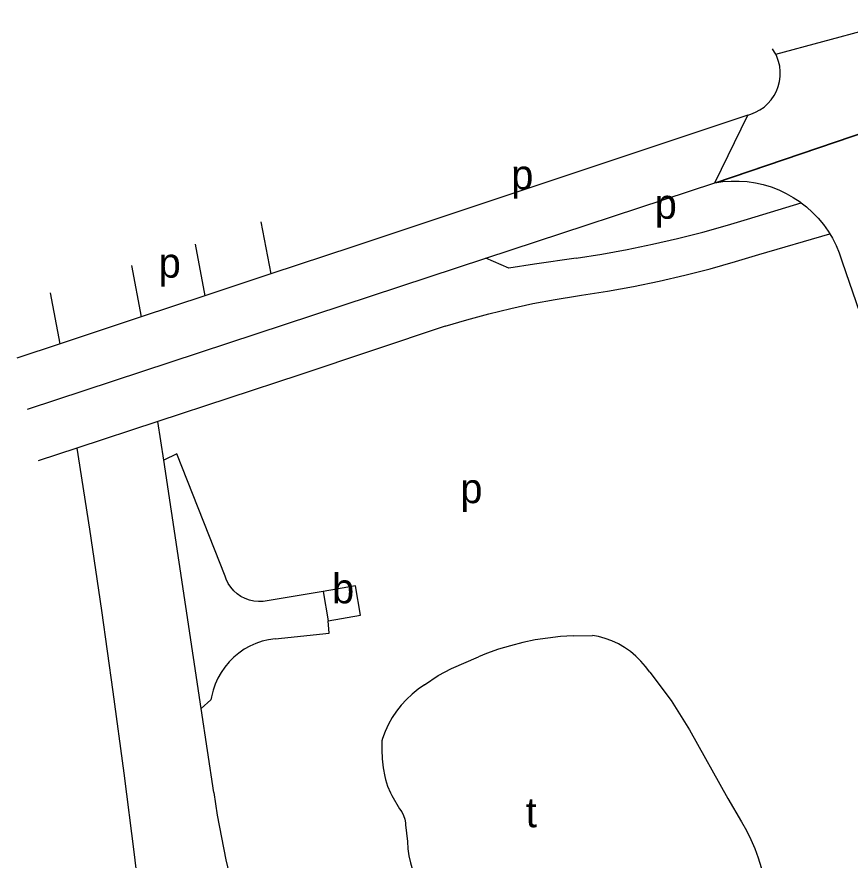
# Model space of a CAD drawing. Extents: x 161936 to 163647, y 386450 to 388633.
# Drawn here: x 162087.7 to 162199.4, y 388398.4 to 388511.6 of the extents above; entities that cross this region are included whole.
import ezdxf

# ---------------------------------------------------------------- set-up
doc = ezdxf.new("R2010")
doc.units = 0
for name, color, linetype in [('BLT_Basislijn', 7, 'Continuous'), ('BLT_Bebouwing', 7, 'Continuous'), ('BLT_Centroide', 7, 'Continuous'), ('BLT_Vlakafsluiter', 7, 'Continuous')]:
    doc.layers.add(name, color=color, linetype=linetype)

msp = doc.modelspace()

# ---------------------------------------------------------------- linework, layer by layer
at = {"layer": 'BLT_Basislijn'}
for p, q in [((162185.68, 388484.43), (162192.85, 388486.62)), ((162187.18, 388479.66), (162196.71, 388482.43)), ((162198.38, 388478.67), (162217.49, 388422.65)), ((162145.13, 388470.05), (162125.65, 388463.55)), ((162125.65, 388463.55), (162106.61, 388457.28)), ((162106.61, 388457.28), (162095.76, 388453.7)), ((162107.4, 388452.07), (162106.61, 388457.28)), ((162095.76, 388453.7), (162090.58, 388451.99)), ((162112.42, 388418.77), (162107.4, 388452.07)), ((162128.79, 388434.47), (162120.72, 388433.13)), ((162162.28, 388428.52), (162164.88, 388428.58)), ((162113.73, 388419.92), (162112.42, 388418.77)), ((162114.11, 388407.51), (162112.42, 388418.77)), ((162137.96, 388407.11), (162139.02, 388405.31)), ((162183.05, 388406.69), (162184.87, 388403.57)), ((162139.82, 388403.19), (162140.1, 388400.92))]:
    msp.add_line(p, q, dxfattribs=at)
for points in [[(162189.46, 388506.53), (162189.31, 388506.83), (162189.03, 388507.27)], [(162185.69, 388498.37), (162186.11, 388498.49), (162186.74, 388498.75), (162187.34, 388499.07), (162187.9, 388499.46), (162188.4, 388499.92), (162188.85, 388500.43), (162189.23, 388500.99), (162189.55, 388501.59), (162189.79, 388502.23), (162189.96, 388502.89), (162190.05, 388503.56), (162190.06, 388504.24), (162189.99, 388504.92), (162189.84, 388505.58), (162189.61, 388506.22), (162189.46, 388506.53)], [(162185.69, 388498.37), (162132.73, 388480.72), (162121.74, 388477.08)], [(162150.58, 388479.17), (162181.28, 388489.3)], [(162181.28, 388489.3), (162181.55, 388489.34)], [(162181.55, 388489.34), (162182.36, 388489.45), (162183.46, 388489.53), (162184.55, 388489.53), (162185.64, 388489.45), (162186.72, 388489.29), (162187.79, 388489.05), (162188.84, 388488.73), (162189.86, 388488.34), (162190.85, 388487.87), (162191.81, 388487.33), (162192.72, 388486.73), (162192.85, 388486.62)], [(162192.85, 388486.62), (162193.58, 388486.05), (162194.4, 388485.32), (162195.15, 388484.53), (162195.85, 388483.69), (162196.49, 388482.8), (162196.71, 388482.43)], [(162162.71, 388479.16), (162166.13, 388479.71), (162169.53, 388480.33), (162172.93, 388481.04), (162176.3, 388481.82), (162179.66, 388482.68), (162182.99, 388483.61), (162185.68, 388484.43)], [(162120.42, 388484.06), (162121.74, 388477.08)], [(162196.71, 388482.43), (162197.05, 388481.86), (162197.55, 388480.89), (162197.98, 388479.88), (162198.33, 388478.84), (162198.38, 388478.67)], [(162111.61, 388481.08), (162112.92, 388474.15)], [(162089.14, 388458.91), (162150.58, 388479.17)], [(162162.71, 388479.16), (162157.09, 388478.39), (162153.65, 388477.84), (162150.58, 388479.17)], [(162163.43, 388474.22), (162166.91, 388474.77), (162170.38, 388475.4), (162173.83, 388476.11), (162177.26, 388476.9), (162180.67, 388477.77), (162184.06, 388478.72), (162187.18, 388479.66)], [(162103.05, 388478.18), (162104.35, 388471.31)], [(162121.74, 388477.08), (162112.92, 388474.15)], [(162093.49, 388467.71), (162092.2, 388474.51)], [(162112.92, 388474.15), (162104.35, 388471.31)], [(162145.13, 388470.05), (162148.04, 388470.92), (162150.97, 388471.72), (162153.92, 388472.44), (162156.89, 388473.08), (162159.88, 388473.65), (162162.88, 388474.14), (162163.43, 388474.22)], [(162104.35, 388471.31), (162093.49, 388467.71)], [(162093.49, 388467.71), (162087.7, 388465.79)], [(162095.76, 388453.7), (162097.45, 388442.82), (162099.06, 388431.93), (162100.59, 388421.03), (162102.04, 388410.11), (162103.42, 388399.19), (162104.71, 388388.26), (162105.92, 388377.32), (162107.06, 388366.37), (162108.11, 388355.41), (162109.09, 388344.45), (162109.98, 388333.48), (162110.35, 388328.63)], [(162115.64, 388436.53), (162109.15, 388452.95), (162107.4, 388452.07)], [(162120.72, 388433.13), (162120.1, 388433.11), (162119.49, 388433.16), (162118.88, 388433.3), (162118.3, 388433.51), (162117.75, 388433.79), (162117.25, 388434.15), (162116.79, 388434.56), (162116.39, 388435.03), (162116.05, 388435.55), (162115.78, 388436.11), (162115.64, 388436.53)], [(162122.32, 388428.13), (162129.57, 388428.89), (162129.46, 388430.55)], [(162122.32, 388428.13), (162121.45, 388428), (162120.59, 388427.79), (162119.76, 388427.5), (162118.95, 388427.14), (162118.18, 388426.71), (162117.46, 388426.21), (162116.78, 388425.64), (162116.16, 388425.02), (162115.6, 388424.34), (162115.1, 388423.62), (162114.66, 388422.85), (162114.3, 388422.05), (162114.02, 388421.22), (162113.81, 388420.36), (162113.73, 388419.92)], [(162162.28, 388428.52), (162160.58, 388428.42), (162158.89, 388428.23), (162157.21, 388427.97), (162155.54, 388427.62), (162153.89, 388427.2), (162152.26, 388426.71), (162150.66, 388426.13), (162149.62, 388425.71)], [(162172.56, 388423.65), (162172, 388424.42), (162171.38, 388425.14), (162170.7, 388425.8), (162169.96, 388426.41), (162169.18, 388426.95), (162168.35, 388427.43), (162167.49, 388427.83), (162166.6, 388428.17), (162165.68, 388428.42), (162164.88, 388428.58)], [(162142.36, 388421.95), (162144.21, 388423.22), (162145.96, 388424.12), (162149.62, 388425.71)], [(162172.56, 388423.65), (162175.42, 388419.83), (162177.91, 388415.91), (162183.05, 388406.69)], [(162142.36, 388421.95), (162141.51, 388421.36), (162140.7, 388420.71), (162139.94, 388420), (162139.24, 388419.24), (162138.6, 388418.42), (162138.03, 388417.55), (162137.53, 388416.65), (162137.09, 388415.7), (162136.74, 388414.73), (162136.64, 388414.42)], [(162136.64, 388414.42), (162136.62, 388413.22), (162136.67, 388412.02), (162136.81, 388410.83), (162137.02, 388409.64), (162137.12, 388409.23)], [(162137.12, 388409.23), (162137.41, 388408.34), (162137.78, 388407.48), (162137.96, 388407.11)], [(162114.11, 388407.51), (162114.58, 388404.48), (162115.12, 388401.46), (162115.74, 388398.46), (162116.44, 388395.47), (162117.21, 388392.51), (162118.07, 388389.56), (162119, 388386.64), (162120.01, 388383.75), (162121.09, 388380.88), (162122.24, 388378.04), (162123.47, 388375.23), (162124.78, 388372.45), (162126.15, 388369.71), (162127.6, 388367.01), (162129.11, 388364.35), (162130.7, 388361.72), (162132.22, 388359.34)], [(162139.02, 388405.31), (162139.33, 388404.89), (162139.56, 388404.43), (162139.72, 388403.93), (162139.81, 388403.42), (162139.82, 388403.19)], [(162184.87, 388403.57), (162185.53, 388402.42), (162186.13, 388401.22), (162186.65, 388399.99), (162187.1, 388398.73), (162187.48, 388397.44), (162187.77, 388396.14), (162187.99, 388394.82), (162188.13, 388393.49), (162188.19, 388392.15), (162188.17, 388390.81), (162188.07, 388389.48), (162187.94, 388388.47)], [(162140.1, 388400.92), (162140.14, 388399.96), (162140.26, 388399.01), (162140.46, 388398.07), (162140.74, 388397.15), (162141, 388396.47)]]:
    msp.add_lwpolyline(points, dxfattribs=at)
at = {"layer": 'BLT_Bebouwing'}
msp.add_line((162128.79, 388434.47), (162129.46, 388430.55), dxfattribs=at)
msp.add_lwpolyline([(162129.46, 388430.55), (162133.78, 388431.3), (162133.11, 388435.21), (162128.79, 388434.47)], dxfattribs=at)
at = {"layer": 'BLT_Vlakafsluiter'}
for p, q in [((162189.46, 388506.53), (162208.07, 388511.55)), ((162181.28, 388489.3), (162212.45, 388499.89)), ((162181.55, 388489.34), (162212.21, 388499.75))]:
    msp.add_line(p, q, dxfattribs=at)
msp.add_lwpolyline([(162181.28, 388489.3), (162185.69, 388498.37)], dxfattribs=at)

# ---------------------------------------------------------------- texts
at = {"layer": 'BLT_Centroide'}
for s, p in [('p', (162153.98, 388488.39)), ('p', (162173.22, 388484.47)), ('p', (162106.71, 388476.57)), ('p', (162147.16, 388446.32)), ('b', (162129.96, 388432.88)), ('t', (162155.93, 388402.84))]:
    msp.add_text(s, height=4, dxfattribs=at).set_placement(p)

doc.saveas('drawing.dxf')
